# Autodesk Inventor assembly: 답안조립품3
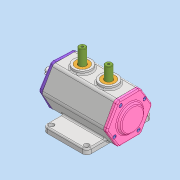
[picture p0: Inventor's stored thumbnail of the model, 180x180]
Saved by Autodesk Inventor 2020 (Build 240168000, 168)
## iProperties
Created: 2021-06
Part Number: 답안조립품3
Document SubType Name: Assembly
Designer: MIRAE
Author: MIRAE
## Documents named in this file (11)
- C:\Users\MIRAE\Desktop\710606V1014\답안조립품3.iam
- C:\Users\MIRAE\Desktop\710606V1014\본체2.ipt
- C:\Users\MIRAE\Desktop\710606V1014\베어링 6302.ipt
- C:\Users\MIRAE\Desktop\710606V1014\편심축.ipt
- C:\Users\MIRAE\Desktop\710606V1014\슬라이더.ipt
- C:\Users\MIRAE\Desktop\710606V1014\베어링 6203.ipt
- C:\Users\MIRAE\Desktop\710606V1014\부시.ipt
- C:\Users\MIRAE\Desktop\710606V1014\뒷커버.ipt
- C:\Users\MIRAE\Desktop\710606V1014\볼트 M4.ipt
- C:\Users\MIRAE\Desktop\710606V1014\오일실.ipt
- C:\Users\MIRAE\Desktop\710606V1014\앞커버.ipt
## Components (6 placed, 3 different names)
1. 7-베어링 6203:1
2. 9-M4-소켓머리:2
3. 9-M4-소켓머리:3
4. 9-M4-소켓머리:4
5. 9-M4-소켓머리:5
6. 8-오일실:1
